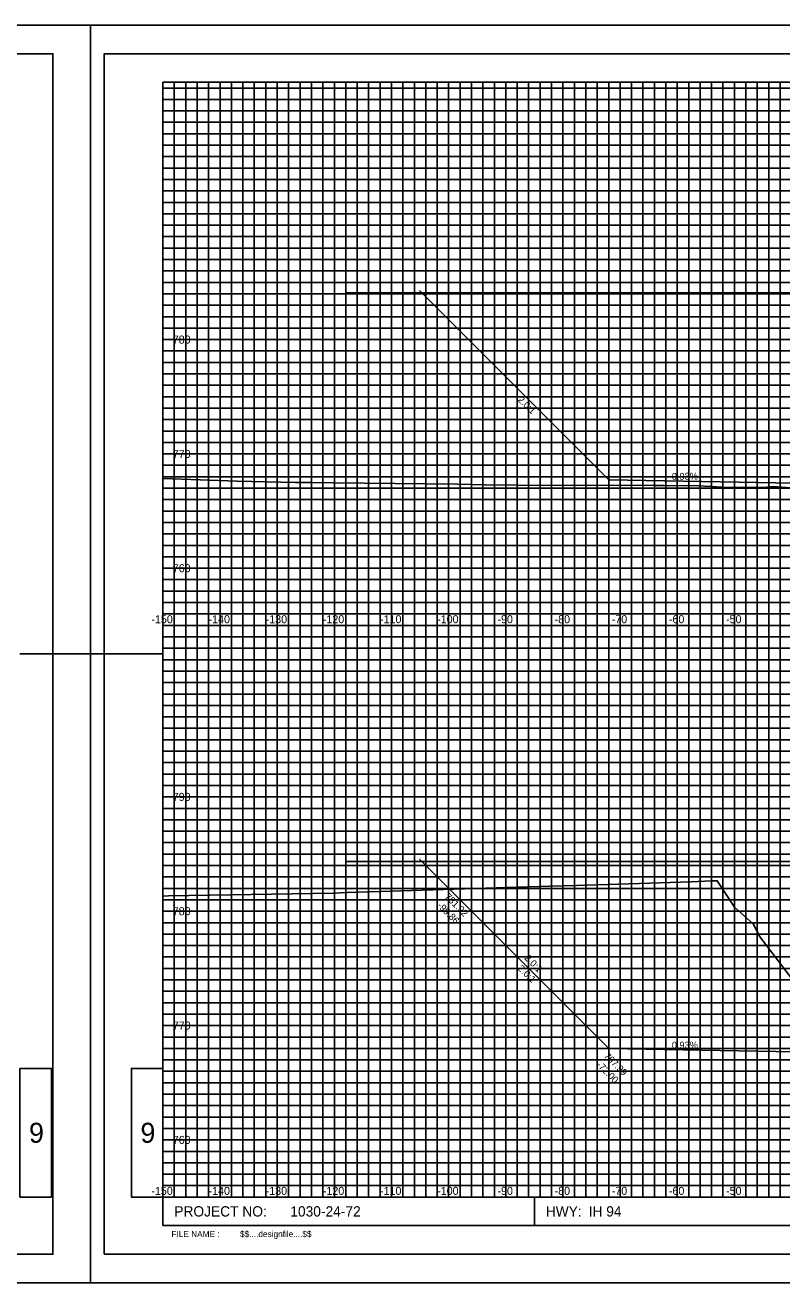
# Model space of a CAD drawing. Extents: x 578243 to 601557, y 174899 to 175559.
# Drawn here: x 600865.7 to 600998.1, y 175338.8 to 175558.8 of the extents above; entities that cross this region are included whole.
import ezdxf

# ---------------------------------------------------------------- set-up
doc = ezdxf.new("R2010")
doc.units = 0
for name, color, linetype in [('E_PROF_Grid', 7, 'Continuous'), ('E_PROF_GridMin', 7, 'Continuous'), ('P_CRDR_Label', 7, 'Continuous'), ('P_CRDR_Link', 7, 'Continuous'), ('P_E_XS_Ground', 7, 'Continuous'), ('P_RW_SlopeIntercepts', 7, 'Continuous'), ('P_XS_Text', 7, 'Continuous'), ('PLT_Sheet_Border', 7, 'Continuous'), ('PLT_Sheet_Info', 7, 'Continuous')]:
    doc.layers.add(name, color=color, linetype=linetype)

msp = doc.modelspace()

# ---------------------------------------------------------------- linework, layer by layer
at = {"layer": 'E_PROF_Grid'}
for p, q in [((600899.84, 175353.8), (600899.84, 175548.8)), ((600909.84, 175353.8), (600909.84, 175548.8)), ((600919.84, 175353.8), (600919.84, 175548.8)), ((600929.84, 175353.8), (600929.84, 175548.8)), ((600939.84, 175353.8), (600939.84, 175548.8)), ((600949.84, 175353.8), (600949.84, 175548.8)), ((600959.84, 175353.8), (600959.84, 175548.8)), ((600969.84, 175353.8), (600969.84, 175548.8)), ((600979.84, 175353.8), (600979.84, 175548.8)), ((600989.84, 175353.8), (600989.84, 175548.8)), ((600889.84, 175543.8), (601204.84, 175543.8)), ((600889.84, 175533.8), (601204.84, 175533.8)), ((600889.84, 175523.8), (601204.84, 175523.8)), ((600889.84, 175513.8), (601204.84, 175513.8)), ((600889.84, 175503.8), (601204.84, 175503.8)), ((600889.84, 175493.8), (601204.84, 175493.8)), ((600889.84, 175483.8), (601204.84, 175483.8)), ((600889.84, 175473.8), (601204.84, 175473.8)), ((600889.84, 175463.8), (601204.84, 175463.8)), ((600889.84, 175453.8), (601204.84, 175453.8)), ((600889.84, 175443.8), (601204.84, 175443.8)), ((600889.84, 175433.8), (601204.84, 175433.8)), ((600889.84, 175423.8), (601204.84, 175423.8)), ((600889.84, 175413.8), (601204.84, 175413.8)), ((600889.84, 175403.8), (601204.84, 175403.8)), ((600889.84, 175393.8), (601204.84, 175393.8)), ((600889.84, 175383.8), (601204.84, 175383.8)), ((600889.84, 175373.8), (601204.84, 175373.8)), ((600889.84, 175363.8), (601204.84, 175363.8))]:
    msp.add_line(p, q, dxfattribs=at)
at = {"layer": 'E_PROF_GridMin'}
for p, q in [((600889.84, 175547.8), (601204.84, 175547.8)), ((600891.84, 175353.8), (600891.84, 175548.8)), ((600893.84, 175353.8), (600893.84, 175548.8)), ((600895.84, 175353.8), (600895.84, 175548.8)), ((600897.84, 175353.8), (600897.84, 175548.8)), ((600901.84, 175353.8), (600901.84, 175548.8)), ((600903.84, 175353.8), (600903.84, 175548.8)), ((600905.84, 175353.8), (600905.84, 175548.8)), ((600907.84, 175353.8), (600907.84, 175548.8)), ((600911.84, 175353.8), (600911.84, 175548.8)), ((600913.84, 175353.8), (600913.84, 175548.8)), ((600915.84, 175353.8), (600915.84, 175548.8)), ((600917.84, 175353.8), (600917.84, 175548.8)), ((600921.84, 175353.8), (600921.84, 175548.8)), ((600923.84, 175353.8), (600923.84, 175548.8)), ((600925.84, 175353.8), (600925.84, 175548.8)), ((600927.84, 175353.8), (600927.84, 175548.8)), ((600931.84, 175353.8), (600931.84, 175548.8)), ((600933.84, 175353.8), (600933.84, 175548.8)), ((600935.84, 175353.8), (600935.84, 175548.8)), ((600937.84, 175353.8), (600937.84, 175548.8)), ((600941.84, 175353.8), (600941.84, 175548.8)), ((600943.84, 175353.8), (600943.84, 175548.8)), ((600945.84, 175353.8), (600945.84, 175548.8)), ((600947.84, 175353.8), (600947.84, 175548.8)), ((600951.84, 175353.8), (600951.84, 175548.8)), ((600953.84, 175353.8), (600953.84, 175548.8)), ((600955.84, 175353.8), (600955.84, 175548.8)), ((600957.84, 175353.8), (600957.84, 175548.8)), ((600961.84, 175353.8), (600961.84, 175548.8)), ((600963.84, 175353.8), (600963.84, 175548.8)), ((600965.84, 175353.8), (600965.84, 175548.8)), ((600967.84, 175353.8), (600967.84, 175548.8)), ((600971.84, 175353.8), (600971.84, 175548.8)), ((600973.84, 175353.8), (600973.84, 175548.8)), ((600975.84, 175353.8), (600975.84, 175548.8)), ((600977.84, 175353.8), (600977.84, 175548.8)), ((600981.84, 175353.8), (600981.84, 175548.8)), ((600983.84, 175353.8), (600983.84, 175548.8)), ((600985.84, 175353.8), (600985.84, 175548.8)), ((600987.84, 175353.8), (600987.84, 175548.8)), ((600991.84, 175353.8), (600991.84, 175548.8)), ((600993.84, 175353.8), (600993.84, 175548.8)), ((600995.84, 175353.8), (600995.84, 175548.8)), ((600997.84, 175353.8), (600997.84, 175548.8)), ((600889.84, 175545.8), (601204.84, 175545.8)), ((600889.84, 175541.8), (601204.84, 175541.8)), ((600889.84, 175539.8), (601204.84, 175539.8)), ((600889.84, 175537.8), (601204.84, 175537.8)), ((600889.84, 175535.8), (601204.84, 175535.8)), ((600889.84, 175531.8), (601204.84, 175531.8)), ((600889.84, 175529.8), (601204.84, 175529.8)), ((600889.84, 175527.8), (601204.84, 175527.8)), ((600889.84, 175525.8), (601204.84, 175525.8)), ((600889.84, 175521.8), (601204.84, 175521.8)), ((600889.84, 175519.8), (601204.84, 175519.8)), ((600889.84, 175517.8), (601204.84, 175517.8)), ((600889.84, 175515.8), (601204.84, 175515.8)), ((600889.84, 175511.8), (601204.84, 175511.8)), ((600889.84, 175509.8), (601204.84, 175509.8)), ((600889.84, 175507.8), (601204.84, 175507.8)), ((600889.84, 175505.8), (601204.84, 175505.8)), ((600889.84, 175501.8), (601204.84, 175501.8)), ((600889.84, 175499.8), (601204.84, 175499.8)), ((600889.84, 175497.8), (601204.84, 175497.8)), ((600889.84, 175495.8), (601204.84, 175495.8)), ((600889.84, 175491.8), (601204.84, 175491.8)), ((600889.84, 175489.8), (601204.84, 175489.8)), ((600889.84, 175487.8), (601204.84, 175487.8)), ((600889.84, 175485.8), (601204.84, 175485.8)), ((600889.84, 175481.8), (601204.84, 175481.8)), ((600889.84, 175479.8), (601204.84, 175479.8)), ((600889.84, 175477.8), (601204.84, 175477.8)), ((600889.84, 175475.8), (601204.84, 175475.8)), ((600889.84, 175471.8), (601204.84, 175471.8)), ((600889.84, 175469.8), (601204.84, 175469.8)), ((600889.84, 175467.8), (601204.84, 175467.8)), ((600889.84, 175465.8), (601204.84, 175465.8)), ((600889.84, 175461.8), (601204.84, 175461.8)), ((600889.84, 175459.8), (601204.84, 175459.8)), ((600889.84, 175457.8), (601204.84, 175457.8)), ((600889.84, 175455.8), (601204.84, 175455.8)), ((600889.84, 175451.8), (601204.84, 175451.8)), ((600889.84, 175449.8), (601204.84, 175449.8)), ((600889.84, 175447.8), (601204.84, 175447.8)), ((600889.84, 175445.8), (601204.84, 175445.8)), ((600889.84, 175441.8), (601204.84, 175441.8)), ((600889.84, 175439.8), (601204.84, 175439.8)), ((600889.84, 175437.8), (601204.84, 175437.8)), ((600889.84, 175435.8), (601204.84, 175435.8)), ((600889.84, 175431.8), (601204.84, 175431.8)), ((600889.84, 175429.8), (601204.84, 175429.8)), ((600889.84, 175427.8), (601204.84, 175427.8)), ((600889.84, 175425.8), (601204.84, 175425.8)), ((600889.84, 175421.8), (601204.84, 175421.8)), ((600889.84, 175419.8), (601204.84, 175419.8)), ((600889.84, 175417.8), (601204.84, 175417.8)), ((600889.84, 175415.8), (601204.84, 175415.8)), ((600889.84, 175411.8), (601204.84, 175411.8)), ((600889.84, 175409.8), (601204.84, 175409.8)), ((600889.84, 175407.8), (601204.84, 175407.8)), ((600889.84, 175405.8), (601204.84, 175405.8)), ((600889.84, 175401.8), (601204.84, 175401.8)), ((600889.84, 175399.8), (601204.84, 175399.8)), ((600889.84, 175397.8), (601204.84, 175397.8)), ((600889.84, 175395.8), (601204.84, 175395.8)), ((600889.84, 175391.8), (601204.84, 175391.8)), ((600889.84, 175389.8), (601204.84, 175389.8)), ((600889.84, 175387.8), (601204.84, 175387.8)), ((600889.84, 175385.8), (601204.84, 175385.8)), ((600889.84, 175381.8), (601204.84, 175381.8)), ((600889.84, 175379.8), (601204.84, 175379.8)), ((600889.84, 175377.8), (601204.84, 175377.8)), ((600889.84, 175375.8), (601204.84, 175375.8)), ((600889.84, 175371.8), (601204.84, 175371.8)), ((600889.84, 175369.8), (601204.84, 175369.8)), ((600889.84, 175367.8), (601204.84, 175367.8)), ((600889.84, 175365.8), (601204.84, 175365.8)), ((600889.84, 175361.8), (601204.84, 175361.8)), ((600889.84, 175359.8), (601204.84, 175359.8)), ((600889.84, 175357.8), (601204.84, 175357.8)), ((600889.84, 175355.8), (601204.84, 175355.8)), ((600877.19, 175338.8), (600877.19, 175348.8)), ((600867.19, 175338.8), (600877.19, 175338.8))]:
    msp.add_line(p, q, dxfattribs=at)
at = {"layer": 'P_CRDR_Link'}
for p, q in [((600934.72, 175512.4), (600967.84, 175479.28)), ((600934.72, 175412.9), (600967.84, 175379.78))]:
    msp.add_line(p, q, dxfattribs=at)
for points in [[(601000.34, 175478.68), (600967.84, 175479.28)], [(601000.34, 175478.68), (600967.84, 175479.28)], [(600967.84, 175379.78), (600939.98, 175407.64)], [(600967.84, 175379.78), (600939.98, 175407.64)], [(601000.34, 175379.18), (600967.84, 175379.78)], [(601000.34, 175379.18), (600967.84, 175379.78)]]:
    msp.add_lwpolyline(points, dxfattribs=at)
at = {"layer": 'P_E_XS_Ground'}
for points in [[(600889.84, 175479.49), (600889.88, 175479.49), (600902.84, 175479.04), (600913.06, 175478.79), (600915.72, 175478.8), (600919.59, 175478.76), (600941.37, 175478.5), (600946.24, 175478.37), (600957.78, 175478.3), (600964.21, 175478.33), (600975.98, 175478.3), (600977.57, 175478.26), (600983.54, 175478.21), (600987.87, 175477.97), (600989.19, 175477.93), (600994.16, 175477.92), (600994.87, 175477.93), (600996.63, 175478.11), (601000.4, 175477.81)], [(600889.84, 175406.45), (600890.85, 175406.47), (600919.7, 175406.99), (600922.16, 175407.06), (600957.55, 175408.21), (600962.19, 175408.31), (600982.29, 175408.97), (600985.86, 175409.1), (600986.83, 175409.11), (600989.88, 175404.53), (600989.92, 175404.47), (600993.14, 175401.6), (600994.36, 175399.25), (600999.77, 175392.14)]]:
    msp.add_lwpolyline(points, dxfattribs=at)
at = {"layer": 'P_RW_SlopeIntercepts'}
for p, q in [((600921.84, 175511.98), (601181.84, 175511.98)), ((600921.84, 175412.48), (601181.84, 175412.48))]:
    msp.add_line(p, q, dxfattribs=at)
at = {"layer": 'PLT_Sheet_Border'}
for points in [[(600537.19, 175338.8), (600877.19, 175338.8), (600877.19, 175558.8), (600537.19, 175558.8)], [(600877.19, 175338.8), (601217.19, 175338.8), (601217.19, 175558.8), (600877.19, 175558.8)], [(600539.59, 175343.8), (600870.59, 175343.8), (600870.59, 175553.8), (600539.59, 175553.8)], [(600879.59, 175343.8), (601210.59, 175343.8), (601210.59, 175553.8), (600879.59, 175553.8)]]:
    msp.add_lwpolyline(points, close=True, dxfattribs=at)
at = {"layer": 'PLT_Sheet_Info'}
for p, q in [((600867.19, 175558.8), (600877.19, 175558.8)), ((600877.19, 175548.8), (600877.19, 175558.8)), ((600877.19, 175548.8), (600877.19, 175558.8)), ((600877.19, 175558.8), (600887.19, 175558.8)), ((600889.84, 175548.8), (601204.84, 175548.8)), ((600889.84, 175348.8), (600889.84, 175548.8)), ((600877.19, 175443.8), (600877.19, 175453.8)), ((600877.19, 175443.8), (600877.19, 175453.8)), ((600877.19, 175448.8), (600864.84, 175448.8)), ((600877.19, 175448.8), (600889.84, 175448.8)), ((600889.84, 175353.8), (601204.84, 175353.8)), ((600954.84, 175348.8), (600954.84, 175353.8)), ((600877.19, 175338.8), (600877.19, 175348.8)), ((600889.84, 175348.8), (601204.84, 175348.8)), ((600877.19, 175338.8), (600887.19, 175338.8))]:
    msp.add_line(p, q, dxfattribs=at)
for points in [[(600864.84, 175376.3), (600870.34, 175376.3), (600870.34, 175353.8), (600864.84, 175353.8)], [(600889.84, 175376.3), (600884.34, 175376.3), (600884.34, 175353.8), (600889.84, 175353.8)]]:
    msp.add_lwpolyline(points, close=True, dxfattribs=at)

# ---------------------------------------------------------------- texts
at = {"layer": 'P_CRDR_Label'}
for s, rotation, p in [('2.0:1', 315.8532, (600951.83, 175493.17)), ('0.93%', 0.4313, (600978.9, 175479.27)), ('781.92', 315, (600939.06, 175406.23)), ('781.92', 315, (600939.06, 175406.23)), ('-99.86', 315, (600937.77, 175404.67)), ('-99.86', 315, (600937.77, 175404.67)), ('2.0:1', 315, (600953, 175395.52)), ('2.0:1', 315.8532, (600951.83, 175393.67)), ('0.93%', 0.4313, (600978.9, 175379.77)), ('767.99', 315, (600966.91, 175378.37)), ('-72.00', 315, (600965.62, 175376.82))]:
    msp.add_text(s, height=1.2, rotation=rotation, dxfattribs=at).set_placement(p)
at = {"layer": 'P_XS_Text'}
for s, p in [('780', (600891.57, 175503.1)), ('770', (600891.57, 175483.1)), ('760', (600891.57, 175463.1)), ('-150', (600887.83, 175454.18)), ('-140', (600897.83, 175454.18)), ('-130', (600907.83, 175454.18)), ('-120', (600917.83, 175454.18)), ('-110', (600927.83, 175454.18)), ('-100', (600937.83, 175454.18)), ('-90', (600948.38, 175454.18)), ('-80', (600958.38, 175454.18)), ('-70', (600968.38, 175454.18)), ('-60', (600978.38, 175454.18)), ('-50', (600988.38, 175454.18)), ('790', (600891.57, 175423.1)), ('780', (600891.57, 175403.1)), ('770', (600891.57, 175383.1)), ('760', (600891.57, 175363.1)), ('-150', (600887.83, 175354.19)), ('-140', (600897.83, 175354.19)), ('-130', (600907.83, 175354.19)), ('-120', (600917.83, 175354.19)), ('-110', (600927.83, 175354.19)), ('-100', (600937.83, 175354.19)), ('-90', (600948.38, 175354.19)), ('-80', (600958.38, 175354.19)), ('-70', (600968.38, 175354.19)), ('-60', (600978.38, 175354.19)), ('-50', (600988.38, 175354.19))]:
    msp.add_text(s, height=1.4, rotation=360, dxfattribs=at).set_placement(p)
at = {"layer": 'PLT_Sheet_Info'}
for s, height, p in [('9', 3.5, (600866.42, 175363.3)), ('9', 3.5, (600885.92, 175363.3)), ('PROJECT NO:', 1.8, (600891.84, 175350.4)), ('1030-24-72             ', 1.8, (600912.14, 175350.4)), ('HWY:', 1.8, (600956.84, 175350.4)), ('IH 94               ', 1.8, (600964.34, 175350.4)), ('FILE NAME :', 1.08, (600891.34, 175346.8))]:
    msp.add_text(s, height=height, dxfattribs=at).set_placement(p)
msp.add_text('$$....designfile....$$', height=1.08, rotation=360, dxfattribs=at).set_placement((600903.34, 175346.8))

doc.saveas('drawing.dxf')
